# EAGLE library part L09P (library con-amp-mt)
AMP MT CONNECTOR
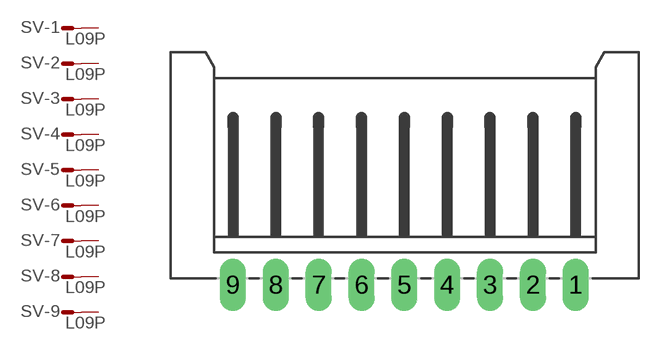
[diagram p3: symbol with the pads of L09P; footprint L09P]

Designator prefix SV; gates -1=M -2=M -3=M -4=M -5=M -6=M -7=M -8=M -9=M

## L09P (OC_FARNELL: unknown; OC_NEWARK: unknown)  [L09P]
1  -1:S  pas
2  -2:S  pas
3  -3:S  pas
4  -4:S  pas
5  -5:S  pas
6  -6:S  pas
7  -7:S  pas
8  -8:S  pas
9  -9:S  pas

## Footprint L09P (pad centres in mm)
AMP MT CONNECTOR
drill 1.016 long: 1 10,-6.25; 2 7.5,-6.25; 3 5,-6.25; 4 2.5,-6.25; 5 0,-6.25; 6 -2.5,-6.25; 7 -5,-6.25; 8 -7.5,-6.25; 9 -10,-6.25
